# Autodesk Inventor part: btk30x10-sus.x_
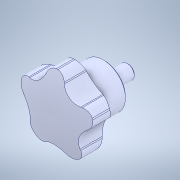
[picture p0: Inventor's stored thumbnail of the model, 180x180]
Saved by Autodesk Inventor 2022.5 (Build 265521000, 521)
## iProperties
Created: 2023-06
Part Number: btk30x10-sus.x_
Material: Generic
Document SubType Name: Modeling
Designer: ImaoCorp
Density: 1 g/cm^3
Appearance: Default
Sending System: SOLIDWORKS 2021-2021301
MC: AMD64
MC_MODEL: Intel64 Family 6 Model 60 Stepping 3, GenuineIntel
OS: Windows_NT
FRU: Parasolid Version 32.1, build 255,  1- 1-2021
FORMAT: text
GUISE: transmit
KEY: btk30x10-sus
FILE: btk30x10-sus.x_t
DATE: Thu Jun 15 15:46:04 2023
Author: ImaoCorp
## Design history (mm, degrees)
feature "Lobe knobs VC.192_30-SST-p-M6x10"
node "ソリッド1"
